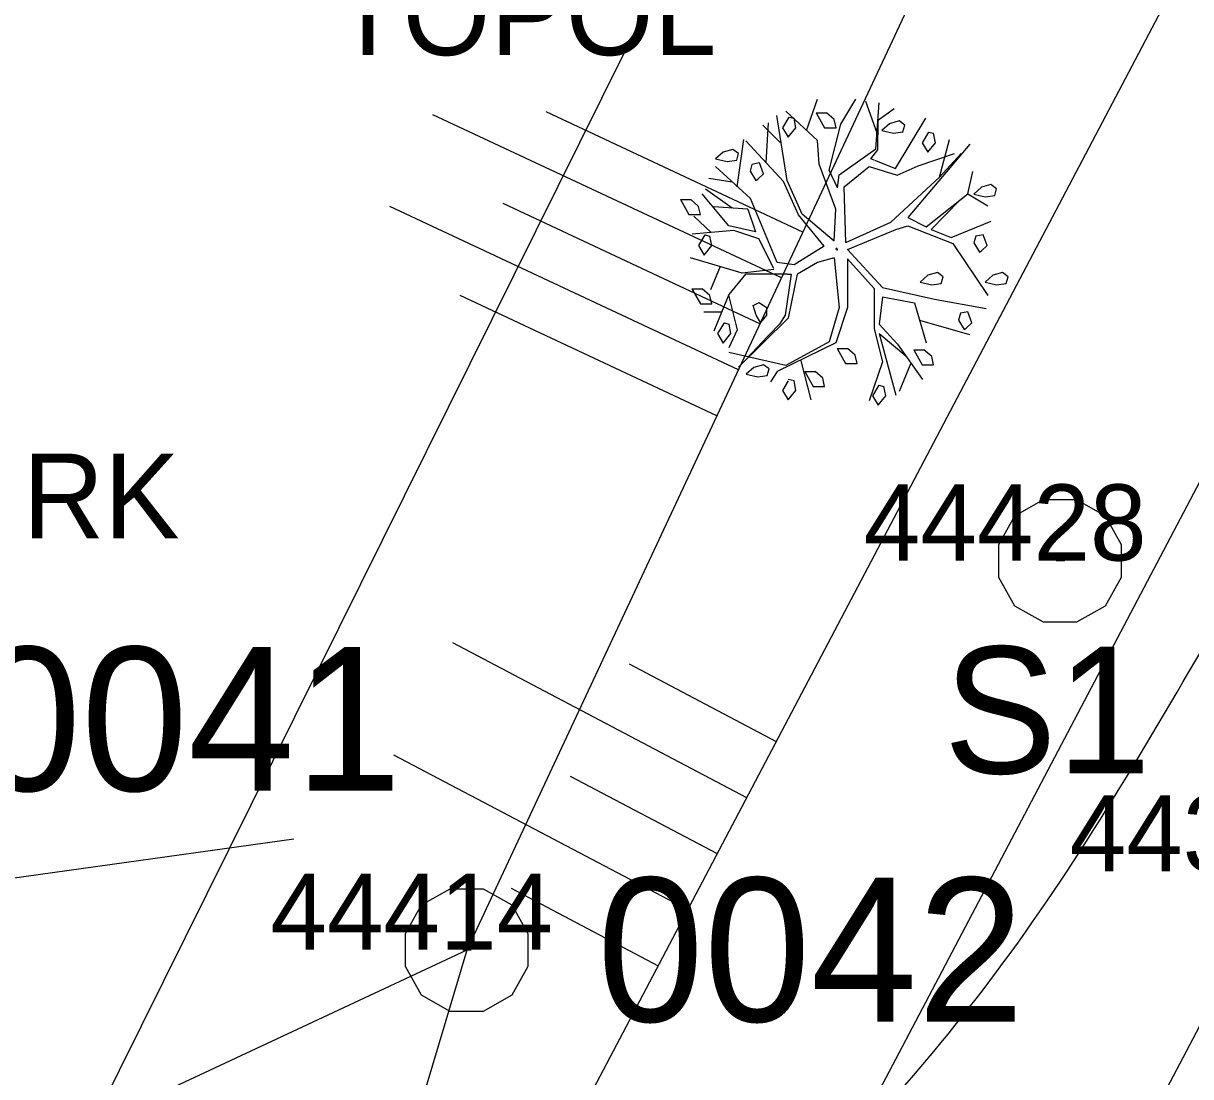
# Model space of a CAD drawing. Extents: x -598521 to -597689, y -1074676 to -1074150.
# Drawn here: x -598484.87 to -598477.96, y -1074178.49 to -1074172.26 of the extents above; entities that cross this region are included whole.
import ezdxf

# ---------------------------------------------------------------- set-up
doc = ezdxf.new("R2010")
doc.units = 0
for name, color, linetype in [('Vrstva 1', 7, 'Continuous'), ('Vrstva 10', 7, 'Continuous'), ('Vrstva 11', 7, 'Continuous'), ('Vrstva 12', 7, 'Continuous'), ('Vrstva 2', 7, 'Continuous'), ('Vrstva 3', 7, 'Continuous'), ('Vrstva 5', 7, 'Continuous'), ('Vrstva 61', 7, 'Continuous')]:
    doc.layers.add(name, color=color, linetype=linetype)

msp = doc.modelspace()

# ---------------------------------------------------------------- linework, layer by layer
at = {"layer": 'Vrstva 1'}
for p, q in [((-598478.755, -1074175.44), (-598478.705, -1074175.44)), ((-598482.267, -1074177.742), (-598482.217, -1074177.742))]:
    msp.add_line(p, q, dxfattribs=at)
for points in [[(-598478.635, -1074175.08), (-598478.465, -1074175.175), (-598478.37, -1074175.345), (-598478.37, -1074175.54), (-598478.465, -1074175.71), (-598478.635, -1074175.805), (-598478.83, -1074175.805), (-598479, -1074175.71), (-598479.095, -1074175.54), (-598479.095, -1074175.345), (-598479, -1074175.175), (-598478.83, -1074175.08)], [(-598482.147, -1074177.382), (-598481.977, -1074177.477), (-598481.882, -1074177.647), (-598481.882, -1074177.842), (-598481.977, -1074178.012), (-598482.147, -1074178.107), (-598482.342, -1074178.107), (-598482.512, -1074178.012), (-598482.607, -1074177.842), (-598482.607, -1074177.647), (-598482.512, -1074177.477), (-598482.342, -1074177.382)]]:
    msp.add_lwpolyline(points, close=True, dxfattribs=at)
at = {"layer": 'Vrstva 10'}
for p, q in [((-598480.2339, -1074172.8955), (-598480.1684, -1074172.711)), ((-598480.0299, -1074172.858), (-598479.9414, -1074172.711)), ((-598479.8159, -1074172.912), (-598479.8819, -1074172.725)), ((-598479.8224, -1074173.005), (-598479.8024, -1074172.732)), ((-598480.3817, -1074173.7686), (-598482.4445, -1074172.8029)), ((-598480.2545, -1074173.4969), (-598481.7739, -1074172.7856)), ((-598480.1684, -1074172.956), (-598480.3564, -1074172.781)), ((-598480.1759, -1074172.792), (-598480.1259, -1074172.88)), ((-598480.1759, -1074172.792), (-598480.1149, -1074172.792)), ((-598480.0694, -1074172.832), (-598480.1149, -1074172.792)), ((-598479.8124, -1074172.837), (-598479.7134, -1074172.767)), ((-598480.3889, -1074172.967), (-598480.4909, -1074172.8655)), ((-598480.4709, -1074173.0885), (-598480.4574, -1074172.851)), ((-598480.3479, -1074173.193), (-598480.4094, -1074172.808)), ((-598480.3369, -1074172.817), (-598480.3749, -1074172.88)), ((-598480.3369, -1074172.817), (-598480.3069, -1074172.824)), ((-598480.2959, -1074172.88), (-598480.3069, -1074172.824)), ((-598480.0994, -1074173.131), (-598480.0299, -1074172.858)), ((-598480.0579, -1074172.88), (-598480.0694, -1074172.832)), ((-598479.8109, -1074173.01), (-598479.8089, -1074172.838)), ((-598479.7414, -1074172.856), (-598479.7864, -1074172.8965)), ((-598479.6844, -1074172.84), (-598479.7414, -1074172.856)), ((-598479.7074, -1074173.1205), (-598479.5264, -1074172.824)), ((-598479.6504, -1074172.864), (-598479.6844, -1074172.84)), ((-598479.6624, -1074172.904), (-598479.6504, -1074172.864)), ((-598480.3749, -1074172.88), (-598480.3409, -1074172.936)), ((-598480.3409, -1074172.936), (-598480.2959, -1074172.88)), ((-598480.1259, -1074172.88), (-598480.0579, -1074172.88)), ((-598479.7864, -1074172.8965), (-598479.7189, -1074172.912)), ((-598479.7189, -1074172.912), (-598479.6624, -1074172.904)), ((-598479.5109, -1074172.9055), (-598479.5489, -1074172.9685)), ((-598479.5109, -1074172.9055), (-598479.4809, -1074172.912)), ((-598479.4699, -1074172.9685), (-598479.4809, -1074172.912)), ((-598480.6689, -1074173.0085), (-598480.7254, -1074173.024)), ((-598480.6354, -1074173.0325), (-598480.6689, -1074173.0085)), ((-598480.6434, -1074173.229), (-598480.6039, -1074172.949)), ((-598480.3684, -1074173.198), (-598480.5929, -1074172.9575)), ((-598480.1584, -1074173.096), (-598480.1684, -1074172.956)), ((-598480.0399, -1074173.159), (-598479.8224, -1074173.005)), ((-598479.8534, -1074173.063), (-598479.8109, -1074173.01)), ((-598479.2669, -1074172.977), (-598479.6344, -1074173.411)), ((-598479.5489, -1074172.9685), (-598479.5149, -1074173.024)), ((-598479.5149, -1074173.024), (-598479.4699, -1074172.9685)), ((-598479.4469, -1074173.173), (-598479.3874, -1074172.949)), ((-598480.7254, -1074173.024), (-598480.7709, -1074173.0645)), ((-598480.7709, -1074173.0645), (-598480.7029, -1074173.0805)), ((-598480.7029, -1074173.0805), (-598480.6464, -1074173.0725)), ((-598480.6464, -1074173.0725), (-598480.6354, -1074173.0325)), ((-598479.8329, -1074173.072), (-598479.8534, -1074173.063)), ((-598479.8314, -1074173.0725), (-598479.7074, -1074173.1205)), ((-598479.5714, -1074173.1045), (-598479.3569, -1074173.0325)), ((-598479.4469, -1074173.173), (-598479.3179, -1074173.033)), ((-598480.5644, -1074173.299), (-598480.7714, -1074173.11)), ((-598480.5559, -1074173.0965), (-598480.5669, -1074173.1365)), ((-598480.5669, -1074173.1365), (-598480.5334, -1074173.1925)), ((-598480.5109, -1074173.0885), (-598480.5559, -1074173.0965)), ((-598480.4879, -1074173.1525), (-598480.5109, -1074173.0885)), ((-598480.0599, -1074173.362), (-598480.1584, -1074173.096)), ((-598480.0499, -1074173.236), (-598480.0994, -1074173.131)), ((-598480.0104, -1074173.229), (-598479.8619, -1074173.11)), ((-598479.8619, -1074173.11), (-598479.6959, -1074173.1605)), ((-598479.6959, -1074173.1605), (-598479.5714, -1074173.1045)), ((-598479.2784, -1074173.271), (-598479.2489, -1074173.138)), ((-598480.6729, -1074173.201), (-598480.8109, -1074173.18)), ((-598480.5334, -1074173.1925), (-598480.5219, -1074173.1845)), ((-598480.5219, -1074173.1845), (-598480.4879, -1074173.1525)), ((-598480.2799, -1074173.3955), (-598480.3684, -1074173.198)), ((-598480.2594, -1074173.391), (-598480.3479, -1074173.193)), ((-598480.0499, -1074173.236), (-598480.0399, -1074173.159)), ((-598479.7334, -1074173.439), (-598479.4469, -1074173.173)), ((-598479.1414, -1074173.2165), (-598479.1979, -1074173.2325)), ((-598479.1079, -1074173.2405), (-598479.1414, -1074173.2165)), ((-598480.6924, -1074173.46), (-598480.8509, -1074173.271)), ((-598480.6724, -1074173.3555), (-598480.8309, -1074173.243)), ((-598480.0004, -1074173.558), (-598480.0104, -1074173.229)), ((-598479.5259, -1074173.467), (-598479.2784, -1074173.271)), ((-598479.2784, -1074173.271), (-598479.1599, -1074173.341)), ((-598479.1979, -1074173.2325), (-598479.2434, -1074173.2725)), ((-598479.2434, -1074173.2725), (-598479.1754, -1074173.2885)), ((-598479.1754, -1074173.2885), (-598479.1189, -1074173.2805)), ((-598479.1189, -1074173.2805), (-598479.1079, -1074173.2405)), ((-598480.6361, -1074174.312), (-598482.6989, -1074173.3463)), ((-598480.5089, -1074174.0403), (-598482.0283, -1074173.329)), ((-598480.9789, -1074173.3045), (-598480.9294, -1074173.393)), ((-598480.9789, -1074173.3045), (-598480.9179, -1074173.3045)), ((-598480.8724, -1074173.345), (-598480.9179, -1074173.3045)), ((-598480.8614, -1074173.393), (-598480.8724, -1074173.345)), ((-598480.5794, -1074173.3615), (-598480.7819, -1074173.348)), ((-598480.4059, -1074173.677), (-598480.5644, -1074173.299)), ((-598479.4959, -1074173.481), (-598479.3259, -1074173.309)), ((-598480.9294, -1074173.393), (-598480.8614, -1074173.393)), ((-598480.7964, -1074173.4995), (-598480.9004, -1074173.404)), ((-598480.5794, -1074173.3615), (-598480.5344, -1074173.495)), ((-598480.1284, -1074173.5805), (-598480.2799, -1074173.3955)), ((-598480.0689, -1074173.55), (-598480.2594, -1074173.391)), ((-598480.0699, -1074173.549), (-598480.0599, -1074173.362)), ((-598479.6344, -1074173.411), (-598479.5259, -1074173.467)), ((-598480.6629, -1074173.488), (-598480.9099, -1074173.509)), ((-598480.5344, -1074173.495), (-598480.6924, -1074173.46)), ((-598480.5144, -1074173.537), (-598480.6629, -1074173.488)), ((-598480.0004, -1074173.558), (-598479.7334, -1074173.439)), ((-598479.9904, -1074173.6), (-598479.7039, -1074173.481)), ((-598479.7039, -1074173.481), (-598479.6344, -1074173.46)), ((-598479.6344, -1074173.46), (-598479.3679, -1074173.565)), ((-598479.4959, -1074173.481), (-598479.3774, -1074173.53)), ((-598479.3774, -1074173.53), (-598479.1399, -1074173.432)), ((-598480.8344, -1074173.514), (-598480.8724, -1074173.577)), ((-598480.8344, -1074173.514), (-598480.8049, -1074173.521)), ((-598480.7934, -1074173.577), (-598480.8049, -1074173.521)), ((-598480.4259, -1074173.712), (-598480.5144, -1074173.537)), ((-598479.2319, -1074173.521), (-598479.2434, -1074173.561)), ((-598479.2434, -1074173.561), (-598479.2094, -1074173.617)), ((-598479.1869, -1074173.513), (-598479.2319, -1074173.521)), ((-598479.1644, -1074173.577), (-598479.1869, -1074173.513)), ((-598480.8724, -1074173.577), (-598480.8389, -1074173.633)), ((-598480.8389, -1074173.633), (-598480.7934, -1074173.577)), ((-598480.1284, -1074173.5805), (-598480.3069, -1074173.691)), ((-598480.0544, -1074173.5985), (-598480.0624, -1074173.5985)), ((-598480.0544, -1074173.5985), (-598480.0544, -1074173.591)), ((-598480.0544, -1074173.5985), (-598480.0544, -1074173.606)), ((-598480.0544, -1074173.5985), (-598480.0469, -1074173.5985)), ((-598479.7839, -1074173.826), (-598479.9904, -1074173.6)), ((-598479.3679, -1074173.565), (-598479.1599, -1074173.873)), ((-598479.2094, -1074173.617), (-598479.1979, -1074173.609)), ((-598479.1979, -1074173.609), (-598479.1644, -1074173.577)), ((-598480.6134, -1074173.74), (-598480.9199, -1074173.649)), ((-598480.7434, -1074173.7015), (-598480.8014, -1074173.838)), ((-598480.3069, -1074173.691), (-598480.4059, -1074173.677)), ((-598480.1684, -1074173.677), (-598480.2874, -1074173.747)), ((-598480.0699, -1074173.649), (-598480.1684, -1074173.677)), ((-598480.0699, -1074173.649), (-598480.0399, -1074173.943)), ((-598479.9904, -1074173.656), (-598479.9904, -1074173.943)), ((-598479.9904, -1074173.656), (-598479.8324, -1074173.831)), ((-598480.5934, -1074173.747), (-598480.6924, -1074173.866)), ((-598480.4259, -1074173.719), (-598480.6134, -1074173.74)), ((-598480.3459, -1074173.747), (-598480.5934, -1074173.747)), ((-598480.3249, -1074173.7465), (-598480.3589, -1074173.989)), ((-598480.3459, -1074173.7465), (-598480.3249, -1074173.7465)), ((-598480.2879, -1074173.7465), (-598480.3409, -1074174.0055)), ((-598480.2879, -1074173.747), (-598480.2874, -1074173.747)), ((-598479.5149, -1074173.753), (-598479.5604, -1074173.793)), ((-598479.4584, -1074173.737), (-598479.5149, -1074173.753)), ((-598479.4244, -1074173.761), (-598479.4584, -1074173.737)), ((-598479.4359, -1074173.801), (-598479.4244, -1074173.761)), ((-598479.1304, -1074173.753), (-598479.1754, -1074173.793)), ((-598479.0739, -1074173.737), (-598479.1304, -1074173.753)), ((-598479.0399, -1074173.761), (-598479.0739, -1074173.737)), ((-598479.0509, -1074173.801), (-598479.0399, -1074173.761)), ((-598480.9114, -1074173.8335), (-598480.8499, -1074173.8335)), ((-598480.9114, -1074173.8335), (-598480.8614, -1074173.9215)), ((-598480.8049, -1074173.873), (-598480.8499, -1074173.8335)), ((-598479.8324, -1074173.831), (-598479.8324, -1074174.069)), ((-598479.7839, -1074173.826), (-598479.4764, -1074173.894)), ((-598479.5604, -1074173.793), (-598479.4924, -1074173.8095)), ((-598479.4924, -1074173.8095), (-598479.4359, -1074173.801)), ((-598479.1754, -1074173.793), (-598479.1079, -1074173.8095)), ((-598479.1079, -1074173.8095), (-598479.0509, -1074173.801)), ((-598480.7633, -1074174.5837), (-598482.2827, -1074173.8724)), ((-598480.7934, -1074173.9215), (-598480.8049, -1074173.873)), ((-598480.6924, -1074173.866), (-598480.7819, -1074174.083)), ((-598480.6954, -1074173.8695), (-598480.6434, -1074174.076)), ((-598479.7829, -1074173.88), (-598479.8024, -1074174.041)), ((-598479.7829, -1074173.88), (-598479.5949, -1074173.915)), ((-598479.4764, -1074173.894), (-598479.1699, -1074173.95)), ((-598480.8614, -1074173.9215), (-598480.7934, -1074173.9215)), ((-598480.7354, -1074173.971), (-598480.8409, -1074173.971)), ((-598480.5489, -1074173.9315), (-598480.5139, -1074173.913)), ((-598480.5314, -1074173.988), (-598480.5489, -1074173.9315)), ((-598480.5139, -1074173.913), (-598480.4699, -1074173.944)), ((-598480.4699, -1074173.944), (-598480.4699, -1074173.988)), ((-598480.0399, -1074173.943), (-598480.0994, -1074174.146)), ((-598479.9904, -1074173.943), (-598480.0599, -1074174.153)), ((-598479.5949, -1074173.915), (-598479.5259, -1074174.153)), ((-598479.3224, -1074173.9775), (-598479.3339, -1074174.0175)), ((-598479.2774, -1074173.9695), (-598479.3224, -1074173.9775)), ((-598479.2549, -1074174.0335), (-598479.2774, -1074173.9695)), ((-598480.7214, -1074174.0345), (-598480.7599, -1074174.098)), ((-598480.7214, -1074174.0345), (-598480.6914, -1074174.0415)), ((-598480.6804, -1074174.098), (-598480.6914, -1074174.0415)), ((-598480.3409, -1074174.0055), (-598480.6354, -1074174.2965)), ((-598480.5049, -1074174.0315), (-598480.5314, -1074173.988)), ((-598480.3934, -1074174.041), (-598480.5094, -1074174.1625)), ((-598480.4699, -1074173.988), (-598480.5049, -1074174.0315)), ((-598480.3589, -1074173.989), (-598480.3934, -1074174.041)), ((-598479.8024, -1074174.041), (-598479.6939, -1074174.16)), ((-598479.5654, -1074174.0175), (-598479.2689, -1074174.104)), ((-598479.3339, -1074174.0175), (-598479.2999, -1074174.0735)), ((-598479.2889, -1074174.0655), (-598479.2549, -1074174.0335)), ((-598480.7599, -1074174.098), (-598480.7254, -1074174.1535)), ((-598480.7254, -1074174.1535), (-598480.6804, -1074174.098)), ((-598480.6434, -1074174.076), (-598480.6924, -1074174.181)), ((-598479.8324, -1074174.069), (-598479.7829, -1074174.265)), ((-598479.8024, -1074174.097), (-598479.7039, -1074174.461)), ((-598479.8024, -1074174.097), (-598479.6449, -1074174.2295)), ((-598479.2999, -1074174.0735), (-598479.2889, -1074174.0655)), ((-598480.5059, -1074174.161), (-598480.5764, -1074174.234)), ((-598480.0599, -1074174.153), (-598480.4059, -1074174.321)), ((-598480.0994, -1074174.146), (-598480.3564, -1074174.286)), ((-598479.6939, -1074174.16), (-598479.5459, -1074174.37)), ((-598480.3564, -1074174.286), (-598480.6924, -1074174.209)), ((-598480.0514, -1074174.186), (-598480.0014, -1074174.274)), ((-598480.0514, -1074174.186), (-598479.9904, -1074174.186)), ((-598479.9449, -1074174.2255), (-598479.9904, -1074174.186)), ((-598479.9334, -1074174.274), (-598479.9449, -1074174.2255)), ((-598479.5984, -1074174.194), (-598479.5489, -1074174.282)), ((-598479.5984, -1074174.194), (-598479.5379, -1074174.194)), ((-598479.4924, -1074174.2335), (-598479.5379, -1074174.194)), ((-598479.4809, -1074174.282), (-598479.4924, -1074174.2335)), ((-598480.5444, -1074174.298), (-598480.5899, -1074174.338)), ((-598480.4879, -1074174.282), (-598480.5444, -1074174.298)), ((-598480.4544, -1074174.306), (-598480.4879, -1074174.282)), ((-598480.4654, -1074174.346), (-598480.4544, -1074174.306)), ((-598480.4059, -1074174.321), (-598480.4454, -1074174.384)), ((-598480.2674, -1074174.258), (-598480.2079, -1074174.489)), ((-598480.2439, -1074174.322), (-598480.1824, -1074174.322)), ((-598480.2439, -1074174.322), (-598480.1939, -1074174.41)), ((-598480.1369, -1074174.362), (-598480.1824, -1074174.322)), ((-598480.0014, -1074174.274), (-598479.9334, -1074174.274)), ((-598479.7829, -1074174.265), (-598479.8619, -1074174.496)), ((-598479.6149, -1074174.272), (-598479.6839, -1074174.44)), ((-598479.5489, -1074174.282), (-598479.4809, -1074174.282)), ((-598480.5899, -1074174.338), (-598480.5219, -1074174.354)), ((-598480.5219, -1074174.354), (-598480.4654, -1074174.346)), ((-598480.3409, -1074174.378), (-598480.3749, -1074174.434)), ((-598480.3069, -1074174.378), (-598480.3409, -1074174.37)), ((-598480.2959, -1074174.434), (-598480.3069, -1074174.378)), ((-598480.1259, -1074174.41), (-598480.1369, -1074174.362)), ((-598480.3749, -1074174.434), (-598480.3409, -1074174.49)), ((-598480.3409, -1074174.49), (-598480.2959, -1074174.434)), ((-598480.1939, -1074174.41), (-598480.1259, -1074174.41)), ((-598479.8049, -1074174.403), (-598479.8434, -1074174.466)), ((-598479.8049, -1074174.403), (-598479.7754, -1074174.41)), ((-598479.7639, -1074174.466), (-598479.7754, -1074174.41)), ((-598479.8434, -1074174.466), (-598479.8089, -1074174.522)), ((-598479.8089, -1074174.522), (-598479.7639, -1074174.466))]:
    msp.add_line(p, q, dxfattribs=at)
for points in [[(-598484.92, -1074215.7337), (-598487.9579, -1074208.4906), (-598488.57, -1074195.13), (-598485.9708, -1074186.4457), (-598483.5857, -1074182.2408), (-598482.242, -1074177.742), (-598479.4514, -1074171.7816), (-598475.091, -1074167.2), (-598468.6388, -1074162.1881), (-598465.6353, -1074160.81), (-598454.605, -1074159.518), (-598444.7168, -1074161.4637), (-598440.4465, -1074163.5641)], [(-598488.57, -1074195.13), (-598487.78, -1074186.27), (-598487.93, -1074180.4), (-598482.242, -1074177.742)]]:
    msp.add_lwpolyline(points, dxfattribs=at)
at = {"layer": 'Vrstva 11'}
for p, q in [((-598480.5857, -1074176.8435), (-598482.3254, -1074175.9272)), ((-598480.4109, -1074176.5117), (-598481.2808, -1074176.0535)), ((-598480.9351, -1074177.5071), (-598482.6749, -1074176.5908)), ((-598480.7604, -1074177.1753), (-598481.6303, -1074176.7171)), ((-598497.4898, -1074179.0592), (-598483.2663, -1074177.0873)), ((-598481.1099, -1074177.8389), (-598481.9798, -1074177.3807))]:
    msp.add_line(p, q, dxfattribs=at)
at = {"layer": 'Vrstva 12'}
for points in [[(-598477.8556, -1074175.904), (-598479.1078, -1074177.8729), (-598481.8726, -1074181.1437), (-598482.7141, -1074182.6203), (-598484.1249, -1074188.1901), (-598485.3348, -1074196.141), (-598485.1135, -1074200.3642), (-598484.5003, -1074206.6546), (-598482.5365, -1074211.2544), (-598480.2074, -1074214.488), (-598467.7934, -1074210.2137), (-598459.7245, -1074208.727), (-598453.744, -1074207.7606), (-598434.0451, -1074202.2598), (-598426.9437, -1074195.6068), (-598420.2001, -1074189.3976), (-598414.7551, -1074180.1636), (-598419.1594, -1074177.7291), (-598424.716, -1074175.6663), (-598432.261, -1074171.9495), (-598446.2733, -1074165.3337), (-598449.2839, -1074163.0664), (-598455.0784, -1074161.4547), (-598458.6047, -1074161.8006), (-598464.2812, -1074162.7184), (-598468.1115, -1074164.5618), (-598472.2785, -1074167.7063), (-598475.1383, -1074168.2051), (-598476.2523, -1074168.9159), (-598476.9776, -1074169.714), (-598477.6095, -1074175.2054), (-598477.8556, -1074175.904)], [(-598473.7888, -1074172.0394), (-598475.746, -1074175.8952), (-598480.6732, -1074186.045), (-598482.6711, -1074189.5445), (-598484.328, -1074196.2355), (-598484.11, -1074202.3062), (-598483.7681, -1074206.3141), (-598481.2248, -1074209.9404), (-598467.3573, -1074209.7347), (-598459.946, -1074208.1465), (-598451.7203, -1074206.1716), (-598433.8843, -1074198.9435), (-598427.582, -1074193.806), (-598421.589, -1074188.753), (-598417.6645, -1074181.613), (-598423.3772, -1074177.4754), (-598435.6533, -1074170.8396), (-598446.2268, -1074166.1248), (-598452.8538, -1074164.1253), (-598463.5233, -1074165.0858), (-598467.1, -1074166.52), (-598468.2906, -1074167.2623), (-598470.6829, -1074168.7005), (-598473.2194, -1074171.071)], [(-598473.7888, -1074172.0394), (-598475.746, -1074175.8952), (-598480.6732, -1074186.045), (-598482.6711, -1074189.5445), (-598484.328, -1074196.2355), (-598484.11, -1074202.3062), (-598483.7681, -1074206.3141), (-598481.2248, -1074209.9404), (-598467.3573, -1074209.7347), (-598459.946, -1074208.1465), (-598451.7203, -1074206.1716), (-598433.8843, -1074198.9435), (-598427.582, -1074193.806), (-598421.589, -1074188.753), (-598417.6645, -1074181.613), (-598423.3772, -1074177.4754), (-598435.6533, -1074170.8396), (-598446.2268, -1074166.1248), (-598452.8538, -1074164.1253), (-598463.5233, -1074165.0858), (-598467.1, -1074166.52), (-598468.2906, -1074167.2623), (-598470.6829, -1074168.7005), (-598473.2194, -1074171.071)], [(-598473.4477, -1074172.2328), (-598475.5803, -1074175.9222), (-598480.4655, -1074186.1252), (-598482.4005, -1074189.7295), (-598483.9812, -1074196.2295), (-598483.8858, -1074202.2525), (-598483.5459, -1074205.9442), (-598480.979, -1074209.1613), (-598475.1374, -1074210.0743), (-598467.0431, -1074208.9296), (-598460.0568, -1074207.6589), (-598451.8734, -1074205.6941), (-598431.7771, -1074196.4611), (-598429.1063, -1074194.1991), (-598419.8673, -1074184.7966), (-598419.8742, -1074181.8158), (-598423.6897, -1074178.1638), (-598435.5722, -1074171.1597), (-598446.4015, -1074166.5943), (-598452.7964, -1074164.4144), (-598463.3503, -1074165.3956), (-598466.975, -1074166.9354), (-598468.1128, -1074167.5827), (-598470.5929, -1074168.9794), (-598472.889, -1074171.3607)], [(-598473.7761, -1074172.0572), (-598475.7867, -1074175.8047), (-598476.6367, -1074177.2466), (-598477.7617, -1074179.2852), (-598478.7593, -1074181.5122), (-598479.981, -1074184.1107), (-598480.826, -1074187.6229), (-598482.8722, -1074196.6443), (-598480.8844, -1074204.4469), (-598462.2993, -1074205.951), (-598457.6214, -1074205.2443), (-598448.6, -1074200.2357), (-598431.1353, -1074190.0523), (-598425.671, -1074182.3452), (-598436.6403, -1074172.4362), (-598453.1707, -1074165.1777), (-598463.8596, -1074166.401), (-598467.0505, -1074166.6304), (-598468.6224, -1074167.548), (-598470.0019, -1074168.3687), (-598470.7965, -1074168.8969), (-598473.2009, -1074171.085)], [(-598473.5637, -1074171.7263), (-598473.7669, -1074172.3072), (-598475.0125, -1074174.9787), (-598476.3495, -1074177.5683), (-598477.7409, -1074180.061), (-598479.8339, -1074184.2158), (-598479.5177, -1074190.8431), (-598476.2488, -1074195.5914), (-598473.0276, -1074199.1466), (-598469.8303, -1074200.6498), (-598462.5766, -1074200.9362), (-598459.26, -1074200.4351), (-598452.1256, -1074196.4742), (-598447.5683, -1074189.3876), (-598439.1693, -1074180.1773), (-598437.5587, -1074177.6481), (-598452.1674, -1074170.9254), (-598460.9004, -1074168.2052), (-598465.8157, -1074168.2052), (-598470.3418, -1074169.3192), (-598472.0865, -1074170.3667), (-598473.3128, -1074171.4245)]]:
    msp.add_spline(points, degree=3, dxfattribs=at)
at = {"layer": 'Vrstva 5'}
for points in [[(-598483.3337, -1074182.6781), (-598481.9031, -1074179.3449), (-598476.4663, -1074169.0219), (-598468.9156, -1074163.2889), (-598464.7031, -1074161.1101), (-598455.7139, -1074160.0208)], [(-598482.9634, -1074215.5153), (-598486.4007, -1074207.5247), (-598486.9992, -1074195.0216), (-598480.5481, -1074179.9912), (-598475.2942, -1074170.0153), (-598468.1115, -1074164.5618), (-598464.2542, -1074162.5666), (-598455.0784, -1074161.4547), (-598445.3665, -1074162.7662), (-598432.9964, -1074169.0842), (-598417.8663, -1074175.8013), (-598412.373, -1074178.9591)], [(-598480.6405, -1074184.0096), (-598479.1932, -1074180.6375), (-598474.1221, -1074171.0087), (-598467.3075, -1074165.8347), (-598463.8053, -1074164.0232), (-598455.3611, -1074163)]]:
    msp.add_lwpolyline(points, dxfattribs=at)
at = {"layer": 'Vrstva 61'}
msp.add_lwpolyline([(-598485.8603, -1074181.5925), (-598487.3349, -1074191.1127), (-598484.1499, -1074192.4794), (-598480.117, -1074184.0575), (-598478.1523, -1074179.8601), (-598476.74, -1074177.23), (-598476.61, -1074175.53), (-598476.12, -1074174.39), (-598475.2941, -1074173.0131), (-598474.7904, -1074172.1849), (-598474.5643, -1074171.7372), (-598475.5804, -1074171.0698), (-598474.7741, -1074169.8405), (-598473.6512, -1074170.5787), (-598471.036, -1074168.831), (-598467.0813, -1074166.5), (-598463.3939, -1074164.6785), (-598455.3026, -1074163.2951), (-598452.5593, -1074163.5319), (-598452.0844, -1074160.0166), (-598455.7958, -1074159.2248), (-598465.6639, -1074160.2898), (-598478.0736, -1074165.9105)], close=True, dxfattribs=at)

# ---------------------------------------------------------------- texts
at = {"layer": 'Vrstva 10'}
for s, height, p in [('TOPOL', 0.5, (-598483.0327, -1074172.4506)), ('SMRK', 0.5, (-598485.8755, -1074175.3079)), ('S1', 0.75, (-598479.4217, -1074176.6994))]:
    msp.add_text(s, height=height, dxfattribs=at).set_placement(p)
at = {"layer": 'Vrstva 2'}
for s, p in [('0041', (-598485.158, -1074176.802)), ('0042', (-598481.473, -1074178.167))]:
    msp.add_text(s, height=0.85, dxfattribs=at).set_placement(p)
at = {"layer": 'Vrstva 3'}
for s, p in [('44428', (-598479.894, -1074175.44)), ('44392', (-598478.6756, -1074177.2788)), ('44414', (-598483.406, -1074177.742))]:
    msp.add_text(s, height=0.45, dxfattribs=at).set_placement(p)

doc.saveas('drawing.dxf')
